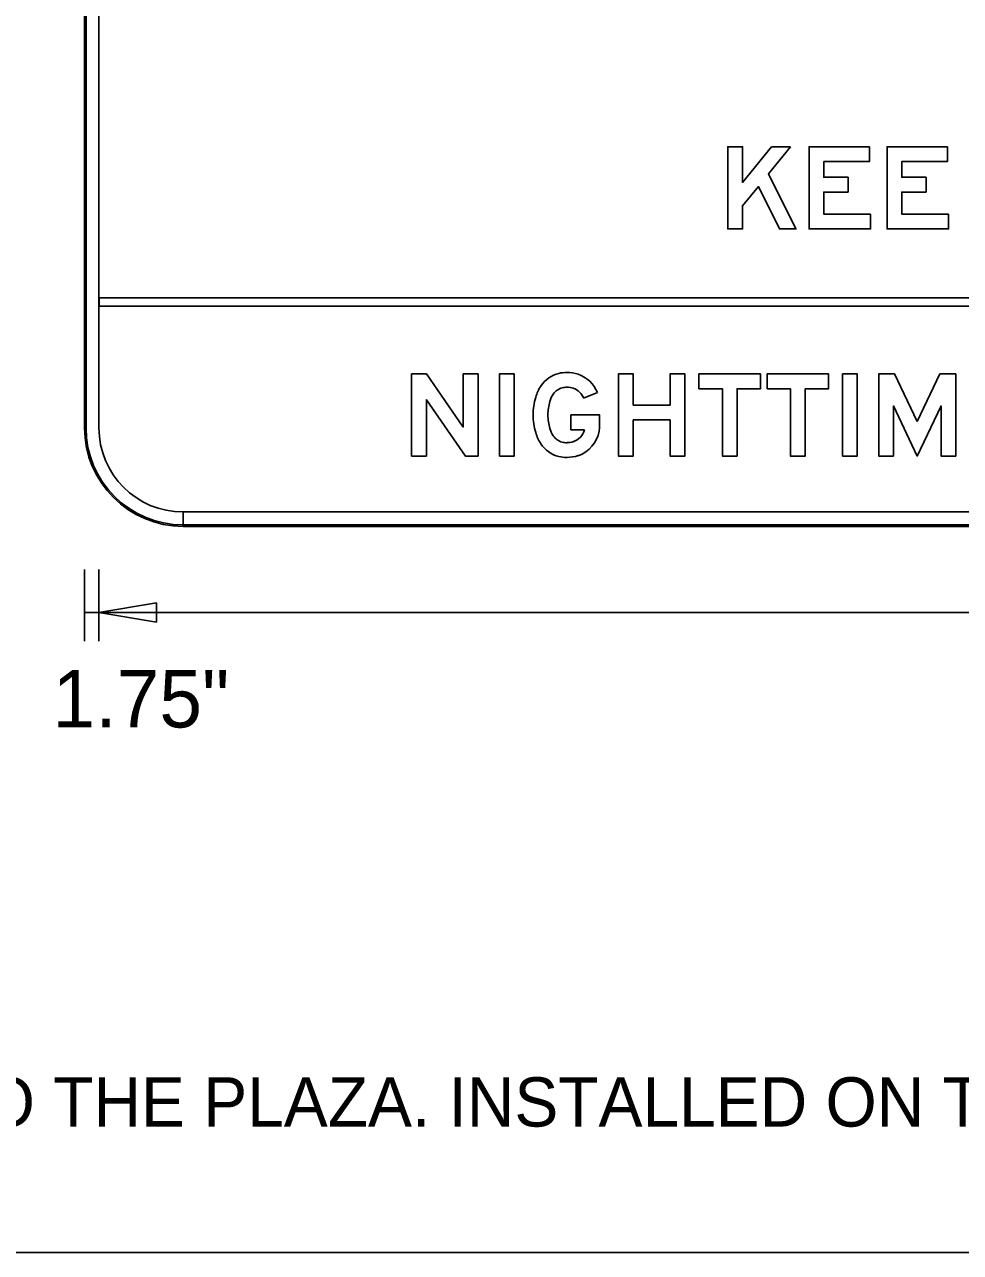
# Model space of a CAD drawing. Extents: x 17890628 to 17890817, y 17897493 to 17897992.
# Drawn here: x 17890698.27 to 17890707.77, y 17897523.4 to 17897535.86 of the extents above; entities that cross this region are included whole.
import ezdxf

# ---------------------------------------------------------------- set-up
doc = ezdxf.new("R2010")
doc.units = 0
for name, color, linetype in [('GSBWFill', 7, 'Continuous'), ('GSColorFill', 7, 'Continuous'), ('GSDims', 7, 'Continuous'), ('GSOutline', 7, 'Continuous'), ('SheetLinesMisc2_dp', 7, 'Continuous')]:
    doc.layers.add(name, color=color, linetype=linetype)

msp = doc.modelspace()

# ---------------------------------------------------------------- linework, layer by layer
at = {"layer": 'GSBWFill'}
for p, q in [((17890698.879, 17897539.769), (17890698.879, 17897531.769)), ((17890699.025, 17897531.769), (17890699.025, 17897539.769)), ((17890718.694, 17897533.087), (17890699.027, 17897533.087)), ((17890699.027, 17897533.087), (17890699.027, 17897533.004)), ((17890699.027, 17897533.004), (17890718.694, 17897533.004)), ((17890699.879, 17897530.769), (17890699.879, 17897530.915)), ((17890717.879, 17897530.915), (17890699.881, 17897530.915)), ((17890699.881, 17897530.915), (17890699.881, 17897530.769)), ((17890699.881, 17897530.769), (17890717.879, 17897530.769))]:
    msp.add_line(p, q, dxfattribs=at)
for points in [[(17890706.047, 17897534.621), (17890705.823, 17897534.346), (17890706.101, 17897533.788), (17890705.934, 17897533.788), (17890705.72, 17897534.218), (17890705.559, 17897534.021), (17890705.559, 17897533.788), (17890705.409, 17897533.788), (17890705.409, 17897534.621), (17890705.559, 17897534.621), (17890705.559, 17897534.259), (17890705.854, 17897534.621)], [(17890706.859, 17897533.938), (17890706.384, 17897533.938), (17890706.384, 17897534.162), (17890706.63, 17897534.162), (17890706.63, 17897534.312), (17890706.384, 17897534.312), (17890706.384, 17897534.471), (17890706.847, 17897534.471), (17890706.847, 17897534.621), (17890706.234, 17897534.621), (17890706.234, 17897533.788), (17890706.859, 17897533.788)], [(17890707.651, 17897533.938), (17890707.176, 17897533.938), (17890707.176, 17897534.162), (17890707.422, 17897534.162), (17890707.422, 17897534.312), (17890707.176, 17897534.312), (17890707.176, 17897534.471), (17890707.639, 17897534.471), (17890707.639, 17897534.621), (17890707.026, 17897534.621), (17890707.026, 17897533.788), (17890707.651, 17897533.788)], [(17890702.874, 17897532.316), (17890702.874, 17897531.483), (17890702.745, 17897531.483), (17890702.349, 17897532.054), (17890702.349, 17897531.483), (17890702.199, 17897531.483), (17890702.199, 17897532.316), (17890702.35, 17897532.316), (17890702.724, 17897531.776), (17890702.724, 17897532.316)], [(17890703.091, 17897531.483), (17890703.091, 17897532.316), (17890703.241, 17897532.316), (17890703.241, 17897531.483)], [(17890704.824, 17897532), (17890704.449, 17897532), (17890704.449, 17897532.316), (17890704.299, 17897532.316), (17890704.299, 17897531.483), (17890704.449, 17897531.483), (17890704.449, 17897531.85), (17890704.824, 17897531.85), (17890704.824, 17897531.483), (17890704.974, 17897531.483), (17890704.974, 17897532.316), (17890704.824, 17897532.316)], [(17890705.116, 17897532.166), (17890705.354, 17897532.166), (17890705.354, 17897531.483), (17890705.504, 17897531.483), (17890705.504, 17897532.166), (17890705.741, 17897532.166), (17890705.741, 17897532.316), (17890705.116, 17897532.316)], [(17890705.808, 17897532.166), (17890706.045, 17897532.166), (17890706.045, 17897531.483), (17890706.195, 17897531.483), (17890706.195, 17897532.166), (17890706.433, 17897532.166), (17890706.433, 17897532.316), (17890705.808, 17897532.316)], [(17890706.574, 17897531.483), (17890706.574, 17897532.316), (17890706.724, 17897532.316), (17890706.724, 17897531.483)], [(17890707.333, 17897531.832), (17890707.563, 17897532.316), (17890707.724, 17897532.316), (17890707.724, 17897531.483), (17890707.574, 17897531.483), (17890707.574, 17897531.991), (17890707.333, 17897531.483), (17890707.091, 17897531.991), (17890707.091, 17897531.483), (17890706.941, 17897531.483), (17890706.941, 17897532.316), (17890707.103, 17897532.316)]]:
    msp.add_lwpolyline(points, close=True, dxfattribs=at)
for points in [[(17890704.085, 17897532.127), (17890703.946, 17897532.071)], [(17890703.953, 17897531.75), (17890703.816, 17897531.75), (17890703.816, 17897531.9), (17890704.108, 17897531.9), (17890704.108, 17897531.78)]]:
    msp.add_lwpolyline(points, dxfattribs=at)
for centre, radius, start, end in [((17890703.763, 17897532.029), 0.3, 103.1315, 146.7742), ((17890703.777, 17897531.969), 0.362, 90, 103.1315), ((17890703.777, 17897531.981), 0.35, 71.2015, 90), ((17890703.785, 17897532.006), 0.324, 22.0367, 71.2015), ((17890703.875, 17897531.956), 0.434, 146.7742, 163.4624), ((17890703.763, 17897532.029), 0.15, 103.1315, 146.7742), ((17890703.777, 17897531.969), 0.212, 90, 103.1315), ((17890703.777, 17897531.981), 0.2, 71.2015, 90), ((17890703.785, 17897532.006), 0.174, 22.0367, 71.2015), ((17890704.064, 17897531.9), 0.631, 163.4624, 180), ((17890704.064, 17897531.9), 0.481, 163.4624, 180), ((17890703.875, 17897531.956), 0.284, 146.7742, 163.4624), ((17890704.064, 17897531.9), 0.631, 180, 196.5376), ((17890704.064, 17897531.9), 0.481, 180, 196.5376), ((17890703.86, 17897531.78), 0.247, 349.6765, 0), ((17890699.879, 17897531.769), 1, 180, 270), ((17890699.879, 17897531.769), 0.854, 180, 270), ((17890703.875, 17897531.844), 0.434, 196.5376, 213.2258), ((17890703.875, 17897531.844), 0.284, 196.5376, 213.2258), ((17890703.763, 17897531.77), 0.15, 213.2258, 256.8685), ((17890703.785, 17897531.793), 0.174, 288.7985, 345.418), ((17890703.785, 17897531.793), 0.324, 288.7985, 349.6765), ((17890703.763, 17897531.77), 0.3, 213.2258, 256.8685), ((17890703.777, 17897531.83), 0.212, 256.8685, 270), ((17890703.777, 17897531.819), 0.2, 270, 288.7985), ((17890703.777, 17897531.83), 0.362, 256.8685, 270), ((17890703.777, 17897531.819), 0.35, 270, 288.7985)]:
    msp.add_arc(centre, radius, start, end, dxfattribs=at)
at = {"layer": 'GSColorFill'}
for p, q in [((17890698.879, 17897539.769), (17890698.879, 17897531.769)), ((17890698.879, 17897539.769), (17890698.879, 17897531.769)), ((17890698.879, 17897539.769), (17890698.879, 17897531.769)), ((17890698.894, 17897531.769), (17890698.894, 17897539.769)), ((17890699.025, 17897531.769), (17890699.025, 17897539.769)), ((17890718.694, 17897533.087), (17890699.027, 17897533.087)), ((17890699.027, 17897533.087), (17890699.027, 17897533.004)), ((17890699.027, 17897533.004), (17890718.694, 17897533.004)), ((17890699.879, 17897530.769), (17890699.879, 17897530.915)), ((17890717.879, 17897530.915), (17890699.881, 17897530.915)), ((17890699.881, 17897530.915), (17890699.881, 17897530.769)), ((17890699.879, 17897530.769), (17890699.879, 17897530.784)), ((17890717.879, 17897530.784), (17890699.88, 17897530.784)), ((17890699.88, 17897530.784), (17890699.88, 17897530.769)), ((17890699.879, 17897530.769), (17890717.879, 17897530.769)), ((17890699.88, 17897530.769), (17890717.879, 17897530.769)), ((17890699.881, 17897530.769), (17890717.879, 17897530.769))]:
    msp.add_line(p, q, dxfattribs=at)
for points in [[(17890706.047, 17897534.621), (17890705.823, 17897534.346), (17890706.101, 17897533.788), (17890705.934, 17897533.788), (17890705.72, 17897534.218), (17890705.559, 17897534.021), (17890705.559, 17897533.788), (17890705.409, 17897533.788), (17890705.409, 17897534.621), (17890705.559, 17897534.621), (17890705.559, 17897534.259), (17890705.854, 17897534.621)], [(17890706.859, 17897533.938), (17890706.384, 17897533.938), (17890706.384, 17897534.162), (17890706.63, 17897534.162), (17890706.63, 17897534.312), (17890706.384, 17897534.312), (17890706.384, 17897534.471), (17890706.847, 17897534.471), (17890706.847, 17897534.621), (17890706.234, 17897534.621), (17890706.234, 17897533.788), (17890706.859, 17897533.788)], [(17890707.651, 17897533.938), (17890707.176, 17897533.938), (17890707.176, 17897534.162), (17890707.422, 17897534.162), (17890707.422, 17897534.312), (17890707.176, 17897534.312), (17890707.176, 17897534.471), (17890707.639, 17897534.471), (17890707.639, 17897534.621), (17890707.026, 17897534.621), (17890707.026, 17897533.788), (17890707.651, 17897533.788)], [(17890702.874, 17897532.316), (17890702.874, 17897531.483), (17890702.745, 17897531.483), (17890702.349, 17897532.054), (17890702.349, 17897531.483), (17890702.199, 17897531.483), (17890702.199, 17897532.316), (17890702.35, 17897532.316), (17890702.724, 17897531.776), (17890702.724, 17897532.316)], [(17890703.091, 17897531.483), (17890703.091, 17897532.316), (17890703.241, 17897532.316), (17890703.241, 17897531.483)], [(17890704.824, 17897532), (17890704.449, 17897532), (17890704.449, 17897532.316), (17890704.299, 17897532.316), (17890704.299, 17897531.483), (17890704.449, 17897531.483), (17890704.449, 17897531.85), (17890704.824, 17897531.85), (17890704.824, 17897531.483), (17890704.974, 17897531.483), (17890704.974, 17897532.316), (17890704.824, 17897532.316)], [(17890705.116, 17897532.166), (17890705.354, 17897532.166), (17890705.354, 17897531.483), (17890705.504, 17897531.483), (17890705.504, 17897532.166), (17890705.741, 17897532.166), (17890705.741, 17897532.316), (17890705.116, 17897532.316)], [(17890705.808, 17897532.166), (17890706.045, 17897532.166), (17890706.045, 17897531.483), (17890706.195, 17897531.483), (17890706.195, 17897532.166), (17890706.433, 17897532.166), (17890706.433, 17897532.316), (17890705.808, 17897532.316)], [(17890706.574, 17897531.483), (17890706.574, 17897532.316), (17890706.724, 17897532.316), (17890706.724, 17897531.483)], [(17890707.333, 17897531.832), (17890707.563, 17897532.316), (17890707.724, 17897532.316), (17890707.724, 17897531.483), (17890707.574, 17897531.483), (17890707.574, 17897531.991), (17890707.333, 17897531.483), (17890707.091, 17897531.991), (17890707.091, 17897531.483), (17890706.941, 17897531.483), (17890706.941, 17897532.316), (17890707.103, 17897532.316)]]:
    msp.add_lwpolyline(points, close=True, dxfattribs=at)
for points in [[(17890704.085, 17897532.127), (17890703.946, 17897532.071)], [(17890703.953, 17897531.75), (17890703.816, 17897531.75), (17890703.816, 17897531.9), (17890704.108, 17897531.9), (17890704.108, 17897531.78)]]:
    msp.add_lwpolyline(points, dxfattribs=at)
for centre, radius, start, end in [((17890703.763, 17897532.029), 0.3, 103.1315, 146.7742), ((17890703.777, 17897531.969), 0.362, 90, 103.1315), ((17890703.777, 17897531.981), 0.35, 71.2015, 90), ((17890703.785, 17897532.006), 0.324, 22.0367, 71.2015), ((17890703.875, 17897531.956), 0.434, 146.7742, 163.4624), ((17890703.763, 17897532.029), 0.15, 103.1315, 146.7742), ((17890703.777, 17897531.969), 0.212, 90, 103.1315), ((17890703.777, 17897531.981), 0.2, 71.2015, 90), ((17890703.785, 17897532.006), 0.174, 22.0367, 71.2015), ((17890704.064, 17897531.9), 0.631, 163.4624, 180), ((17890704.064, 17897531.9), 0.481, 163.4624, 180), ((17890703.875, 17897531.956), 0.284, 146.7742, 163.4624), ((17890704.064, 17897531.9), 0.631, 180, 196.5376), ((17890704.064, 17897531.9), 0.481, 180, 196.5376), ((17890703.86, 17897531.78), 0.247, 349.6765, 0), ((17890699.879, 17897531.769), 1, 180, 270), ((17890699.879, 17897531.769), 1, 180, 270), ((17890699.879, 17897531.769), 1, 180, 270), ((17890699.879, 17897531.769), 0.985, 180, 270), ((17890699.879, 17897531.769), 0.854, 180, 270), ((17890703.875, 17897531.844), 0.434, 196.5376, 213.2258), ((17890703.875, 17897531.844), 0.284, 196.5376, 213.2258), ((17890703.763, 17897531.77), 0.15, 213.2258, 256.8685), ((17890703.785, 17897531.793), 0.174, 288.7985, 345.418), ((17890703.785, 17897531.793), 0.324, 288.7985, 349.6765), ((17890703.763, 17897531.77), 0.3, 213.2258, 256.8685), ((17890703.777, 17897531.83), 0.212, 256.8685, 270), ((17890703.777, 17897531.819), 0.2, 270, 288.7985), ((17890703.777, 17897531.83), 0.362, 256.8685, 270), ((17890703.777, 17897531.819), 0.35, 270, 288.7985)]:
    msp.add_arc(centre, radius, start, end, dxfattribs=at)
at = {"layer": 'GSDims'}
for p, q in [((17890698.88, 17897530.332), (17890698.88, 17897529.603)), ((17890699.025, 17897530.332), (17890699.025, 17897529.603)), ((17890698.88, 17897529.894), (17890699.025, 17897529.894)), ((17890699.025, 17897529.894), (17890718.713, 17897529.894))]:
    msp.add_line(p, q, dxfattribs=at)
msp.add_lwpolyline([(17890699.025, 17897529.894), (17890699.608, 17897529.992), (17890699.608, 17897529.797)], close=True, dxfattribs=at)
at = {"layer": 'GSOutline'}
for p, q in [((17890698.879, 17897539.769), (17890698.879, 17897531.769)), ((17890699.025, 17897539.769), (17890699.025, 17897531.769)), ((17890718.694, 17897533.087), (17890699.027, 17897533.087)), ((17890699.027, 17897533.087), (17890699.027, 17897533.004)), ((17890699.027, 17897533.004), (17890718.694, 17897533.004)), ((17890699.879, 17897530.915), (17890717.879, 17897530.915)), ((17890699.879, 17897530.769), (17890717.879, 17897530.769))]:
    msp.add_line(p, q, dxfattribs=at)
for points in [[(17890706.047, 17897534.621), (17890705.823, 17897534.346), (17890706.101, 17897533.788), (17890705.934, 17897533.788), (17890705.72, 17897534.218), (17890705.559, 17897534.021), (17890705.559, 17897533.788), (17890705.409, 17897533.788), (17890705.409, 17897534.621), (17890705.559, 17897534.621), (17890705.559, 17897534.259), (17890705.854, 17897534.621)], [(17890706.859, 17897533.938), (17890706.384, 17897533.938), (17890706.384, 17897534.162), (17890706.63, 17897534.162), (17890706.63, 17897534.312), (17890706.384, 17897534.312), (17890706.384, 17897534.471), (17890706.847, 17897534.471), (17890706.847, 17897534.621), (17890706.234, 17897534.621), (17890706.234, 17897533.788), (17890706.859, 17897533.788)], [(17890707.651, 17897533.938), (17890707.176, 17897533.938), (17890707.176, 17897534.162), (17890707.422, 17897534.162), (17890707.422, 17897534.312), (17890707.176, 17897534.312), (17890707.176, 17897534.471), (17890707.639, 17897534.471), (17890707.639, 17897534.621), (17890707.026, 17897534.621), (17890707.026, 17897533.788), (17890707.651, 17897533.788)], [(17890702.874, 17897532.316), (17890702.874, 17897531.483), (17890702.745, 17897531.483), (17890702.349, 17897532.054), (17890702.349, 17897531.483), (17890702.199, 17897531.483), (17890702.199, 17897532.316), (17890702.35, 17897532.316), (17890702.724, 17897531.776), (17890702.724, 17897532.316)], [(17890703.091, 17897531.483), (17890703.091, 17897532.316), (17890703.241, 17897532.316), (17890703.241, 17897531.483)], [(17890704.824, 17897532), (17890704.449, 17897532), (17890704.449, 17897532.316), (17890704.299, 17897532.316), (17890704.299, 17897531.483), (17890704.449, 17897531.483), (17890704.449, 17897531.85), (17890704.824, 17897531.85), (17890704.824, 17897531.483), (17890704.974, 17897531.483), (17890704.974, 17897532.316), (17890704.824, 17897532.316)], [(17890705.116, 17897532.166), (17890705.354, 17897532.166), (17890705.354, 17897531.483), (17890705.504, 17897531.483), (17890705.504, 17897532.166), (17890705.741, 17897532.166), (17890705.741, 17897532.316), (17890705.116, 17897532.316)], [(17890705.808, 17897532.166), (17890706.045, 17897532.166), (17890706.045, 17897531.483), (17890706.195, 17897531.483), (17890706.195, 17897532.166), (17890706.433, 17897532.166), (17890706.433, 17897532.316), (17890705.808, 17897532.316)], [(17890706.574, 17897531.483), (17890706.574, 17897532.316), (17890706.724, 17897532.316), (17890706.724, 17897531.483)], [(17890707.333, 17897531.832), (17890707.563, 17897532.316), (17890707.724, 17897532.316), (17890707.724, 17897531.483), (17890707.574, 17897531.483), (17890707.574, 17897531.991), (17890707.333, 17897531.483), (17890707.091, 17897531.991), (17890707.091, 17897531.483), (17890706.941, 17897531.483), (17890706.941, 17897532.316), (17890707.103, 17897532.316)]]:
    msp.add_lwpolyline(points, close=True, dxfattribs=at)
for points in [[(17890704.085, 17897532.127), (17890703.946, 17897532.071)], [(17890703.953, 17897531.75), (17890703.816, 17897531.75), (17890703.816, 17897531.9), (17890704.108, 17897531.9), (17890704.108, 17897531.78)]]:
    msp.add_lwpolyline(points, dxfattribs=at)
for centre, radius, start, end in [((17890703.763, 17897532.029), 0.3, 103.1315, 146.7742), ((17890703.777, 17897531.969), 0.362, 90, 103.1315), ((17890703.777, 17897531.981), 0.35, 71.2015, 90), ((17890703.785, 17897532.006), 0.324, 22.0367, 71.2015), ((17890703.875, 17897531.956), 0.434, 146.7742, 163.4624), ((17890703.763, 17897532.029), 0.15, 103.1315, 146.7742), ((17890703.777, 17897531.969), 0.212, 90, 103.1315), ((17890703.777, 17897531.981), 0.2, 71.2015, 90), ((17890703.785, 17897532.006), 0.174, 22.0367, 71.2015), ((17890704.064, 17897531.9), 0.631, 163.4624, 180), ((17890704.064, 17897531.9), 0.481, 163.4624, 180), ((17890703.875, 17897531.956), 0.284, 146.7742, 163.4624), ((17890704.064, 17897531.9), 0.631, 180, 196.5376), ((17890704.064, 17897531.9), 0.481, 180, 196.5376), ((17890703.86, 17897531.78), 0.247, 349.6765, 0), ((17890699.879, 17897531.769), 1, 180, 270), ((17890699.879, 17897531.769), 0.854, 180, 270), ((17890703.875, 17897531.844), 0.434, 196.5376, 213.2258), ((17890703.875, 17897531.844), 0.284, 196.5376, 213.2258), ((17890703.763, 17897531.77), 0.15, 213.2258, 256.8685), ((17890703.785, 17897531.793), 0.174, 288.7985, 345.418), ((17890703.785, 17897531.793), 0.324, 288.7985, 349.6765), ((17890703.763, 17897531.77), 0.3, 213.2258, 256.8685), ((17890703.777, 17897531.83), 0.212, 256.8685, 270), ((17890703.777, 17897531.819), 0.2, 270, 288.7985), ((17890703.777, 17897531.83), 0.362, 256.8685, 270), ((17890703.777, 17897531.819), 0.35, 270, 288.7985)]:
    msp.add_arc(centre, radius, start, end, dxfattribs=at)
at = {"layer": 'SheetLinesMisc2_dp'}
msp.add_line((17890684.628, 17897523.399), (17890735.8, 17897523.399), dxfattribs=at)

# ---------------------------------------------------------------- texts
at = {"layer": 'GSDims'}
for s, height, p in [('1.75"', 0.5833, (17890698.554, 17897528.728)), ('TYPICAL: FINAL SIGN BEFORE ENTRY TO THE PLAZA. INSTALLED ON THE LEFT IN THE MEDIAN', 0.5, (17890685.001, 17897524.677))]:
    msp.add_text(s, height=height, dxfattribs=at).set_placement(p)

doc.saveas('drawing.dxf')
